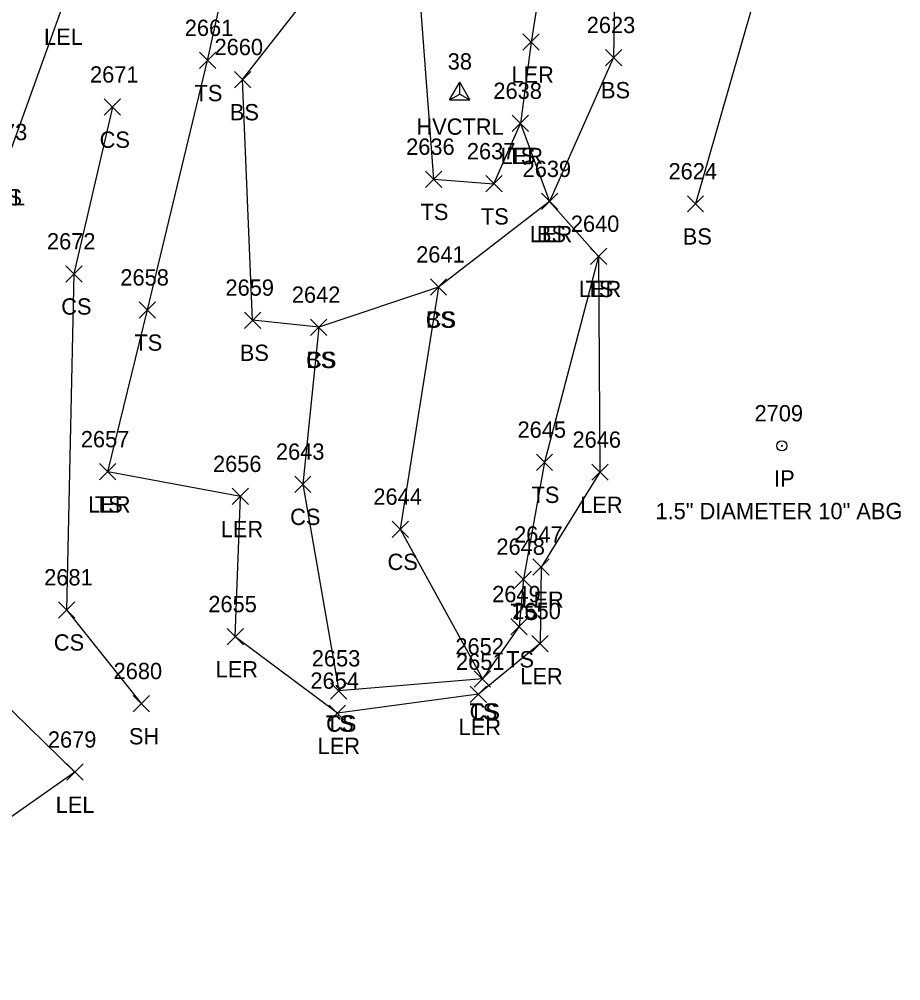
# Model space of a CAD drawing. Extents: x 1483143 to 1488182, y 802902 to 807581.
# Drawn here: x 1487627.8 to 1487735.9, y 805656.4 to 805774.4 of the extents above; entities that cross this region are included whole.
import ezdxf

# ---------------------------------------------------------------- set-up
doc = ezdxf.new("R2010")
doc.units = 0
for name, color, linetype in [('C_A', 7, 'Continuous'), ('C_I', 7, 'Continuous'), ('CPSM', 7, 'Continuous'), ('L_A', 7, 'Continuous'), ('L_I', 7, 'Continuous'), ('L_TIC', 7, 'Continuous'), ('LARO', 7, 'Continuous'), ('LELB', 7, 'Continuous'), ('M_A', 7, 'Continuous'), ('M_C', 7, 'Continuous'), ('M_I', 7, 'Continuous'), ('MPIR', 7, 'Continuous')]:
    doc.layers.add(name, color=color, linetype=linetype)

msp = doc.modelspace()

# ---------------------------------------------------------------- linework, layer by layer
at = {"layer": 'CPSM'}
for p, q in [((1487680.58, 805764.47), (1487681.83, 805766.64)), ((1487683.08, 805764.47), (1487681.83, 805766.64)), ((1487681.83, 805765.19), (1487681.83, 805766.64)), ((1487680.58, 805764.47), (1487681.83, 805765.19)), ((1487680.58, 805764.47), (1487683.08, 805764.47)), ((1487681.83, 805765.19), (1487681.83, 805765.19)), ((1487681.83, 805765.19), (1487683.08, 805764.47))]:
    msp.add_line(p, q, dxfattribs=at)
at = {"layer": 'L_TIC'}
for points in [[(1487689.59, 805770.57), (1487691.59, 805772.57)], [(1487691.59, 805770.57), (1487689.59, 805772.57)], [(1487649.9, 805768.31), (1487651.9, 805770.31)], [(1487651.9, 805768.31), (1487649.9, 805770.31)], [(1487699.71, 805768.66), (1487701.71, 805770.66)], [(1487701.71, 805768.66), (1487699.71, 805770.66)], [(1487654.2, 805765.96), (1487656.2, 805767.96)], [(1487656.2, 805765.96), (1487654.2, 805767.96)], [(1487638.23, 805762.59), (1487640.23, 805764.59)], [(1487640.23, 805762.59), (1487638.23, 805764.59)], [(1487688.27, 805760.59), (1487690.27, 805762.59)], [(1487690.27, 805760.59), (1487688.27, 805762.59)], [(1487688.27, 805760.59), (1487690.27, 805762.59)], [(1487690.27, 805760.59), (1487688.27, 805762.59)], [(1487677.62, 805753.73), (1487679.62, 805755.73)], [(1487679.62, 805753.73), (1487677.62, 805755.73)], [(1487685.02, 805753.18), (1487687.02, 805755.18)], [(1487687.02, 805753.18), (1487685.02, 805755.18)], [(1487691.86, 805751.01), (1487693.86, 805753.01)], [(1487693.86, 805751.01), (1487691.86, 805753.01)], [(1487691.86, 805751.01), (1487693.86, 805753.01)], [(1487693.86, 805751.01), (1487691.86, 805753.01)], [(1487709.75, 805750.72), (1487711.75, 805752.72)], [(1487711.75, 805750.72), (1487709.75, 805752.72)], [(1487697.86, 805744.28), (1487699.86, 805746.28)], [(1487699.86, 805744.28), (1487697.86, 805746.28)], [(1487697.86, 805744.28), (1487699.86, 805746.28)], [(1487699.86, 805744.28), (1487697.86, 805746.28)], [(1487633.52, 805742.13), (1487635.52, 805744.13)], [(1487635.52, 805742.13), (1487633.52, 805744.13)], [(1487678.23, 805740.52), (1487680.23, 805742.52)], [(1487680.23, 805740.52), (1487678.23, 805742.52)], [(1487678.23, 805740.52), (1487680.23, 805742.52)], [(1487680.23, 805740.52), (1487678.23, 805742.52)], [(1487642.52, 805737.7), (1487644.52, 805739.7)], [(1487644.52, 805737.7), (1487642.52, 805739.7)], [(1487655.42, 805736.45), (1487657.42, 805738.45)], [(1487657.42, 805736.45), (1487655.42, 805738.45)], [(1487663.55, 805735.58), (1487665.55, 805737.58)], [(1487665.55, 805735.58), (1487663.55, 805737.58)], [(1487663.55, 805735.58), (1487665.55, 805737.58)], [(1487665.55, 805735.58), (1487663.55, 805737.58)], [(1487691.23, 805719.03), (1487693.23, 805721.03)], [(1487693.23, 805719.03), (1487691.23, 805721.03)], [(1487637.67, 805717.86), (1487639.67, 805719.86)], [(1487639.67, 805717.86), (1487637.67, 805719.86)], [(1487637.67, 805717.86), (1487639.67, 805719.86)], [(1487639.67, 805717.86), (1487637.67, 805719.86)], [(1487698.02, 805717.81), (1487700.02, 805719.81)], [(1487700.02, 805717.81), (1487698.02, 805719.81)], [(1487661.59, 805716.33), (1487663.59, 805718.33)], [(1487663.59, 805716.33), (1487661.59, 805718.33)], [(1487653.93, 805714.83), (1487655.93, 805716.83)], [(1487655.93, 805714.83), (1487653.93, 805716.83)], [(1487673.54, 805710.81), (1487675.54, 805712.81)], [(1487675.54, 805710.81), (1487673.54, 805712.81)], [(1487690.81, 805706.17), (1487692.81, 805708.17)], [(1487692.81, 805706.17), (1487690.81, 805708.17)], [(1487688.64, 805704.67), (1487690.64, 805706.67)], [(1487690.64, 805704.67), (1487688.64, 805706.67)], [(1487632.61, 805700.92), (1487634.61, 805702.92)], [(1487634.61, 805700.92), (1487632.61, 805702.92)], [(1487688.12, 805698.86), (1487690.12, 805700.86)], [(1487690.12, 805698.86), (1487688.12, 805700.86)], [(1487653.3, 805697.63), (1487655.3, 805699.63)], [(1487655.3, 805697.63), (1487653.3, 805699.63)], [(1487690.68, 805696.79), (1487692.68, 805698.79)], [(1487692.68, 805696.79), (1487690.68, 805698.79)], [(1487683.61, 805692.45), (1487685.61, 805694.45)], [(1487685.61, 805692.45), (1487683.61, 805694.45)], [(1487683.61, 805692.45), (1487685.61, 805694.45)], [(1487685.61, 805692.45), (1487683.61, 805694.45)], [(1487666, 805690.98), (1487668, 805692.98)], [(1487668, 805690.98), (1487666, 805692.98)], [(1487666, 805690.98), (1487668, 805692.98)], [(1487668, 805690.98), (1487666, 805692.98)], [(1487683.12, 805690.56), (1487685.12, 805692.56)], [(1487685.12, 805690.56), (1487683.12, 805692.56)], [(1487641.77, 805689.42), (1487643.77, 805691.42)], [(1487643.77, 805689.42), (1487641.77, 805691.42)], [(1487665.83, 805688.24), (1487667.83, 805690.24)], [(1487667.83, 805688.24), (1487665.83, 805690.24)], [(1487633.64, 805681.02), (1487635.64, 805683.02)], [(1487635.64, 805681.02), (1487633.64, 805683.02)]]:
    msp.add_lwpolyline(points, dxfattribs=at)
at = {"layer": 'LARO'}
for points in [[(1487705.29, 805896.34), (1487695.87, 805891.2), (1487689.13, 805878.29), (1487689.57, 805859.67), (1487670.44, 805829.21), (1487659.71, 805823.79), (1487649.08, 805803.93), (1487638.97, 805785.42), (1487633.21, 805776.22), (1487626.14, 805756.53), (1487619.37, 805736.85), (1487617.73, 805704.95), (1487625.22, 805691.16), (1487634.64, 805682.02), (1487622.34, 805673.38), (1487621.2, 805638.86), (1487621.06, 805617.78)], [(1487705.29, 805896.34), (1487704.06, 805875.92), (1487701.89, 805851.18), (1487695.31, 805846.63), (1487693.97, 805826.04), (1487694.06, 805815.15), (1487697.49, 805803.83), (1487704.56, 805795.94), (1487708.81, 805792.59), (1487701.05, 805792.26), (1487694.18, 805794.48), (1487690.59, 805771.57), (1487689.27, 805761.59), (1487692.86, 805752.01), (1487698.86, 805745.28), (1487699.02, 805718.81), (1487691.81, 805707.17), (1487691.68, 805697.79), (1487684.12, 805691.56), (1487666.83, 805689.24), (1487654.3, 805698.63), (1487654.93, 805715.83), (1487638.67, 805718.86)]]:
    msp.add_lwpolyline(points, dxfattribs=at)
at = {"layer": 'LELB'}
for points in [[(1487694.18, 805794.48), (1487693.17, 805806.33), (1487687.93, 805817.69), (1487689.85, 805831.08), (1487691.37, 805841.24), (1487689.57, 805859.67), (1487682.46, 805830.78), (1487680.31, 805810.06), (1487676.2, 805786.76), (1487678.62, 805754.73), (1487686.02, 805754.18), (1487689.27, 805761.59)], [(1487638.67, 805718.86), (1487643.52, 805738.7), (1487650.9, 805769.31), (1487655.79, 805791.53), (1487662.09, 805808.31), (1487670.44, 805829.21)], [(1487701.05, 805792.26), (1487700.71, 805769.66), (1487692.86, 805752.01), (1487679.23, 805741.52), (1487664.55, 805736.58), (1487656.42, 805737.45), (1487655.2, 805766.96), (1487666.09, 805780.93), (1487669.14, 805806.74), (1487670.44, 805829.21)], [(1487719.18, 805781.13), (1487710.75, 805751.72)], [(1487639.23, 805763.59), (1487634.52, 805743.13), (1487633.61, 805701.92)], [(1487698.86, 805745.28), (1487692.23, 805720.03), (1487689.64, 805705.67), (1487689.12, 805699.86), (1487684.61, 805693.45), (1487667, 805691.98)], [(1487679.23, 805741.52), (1487674.54, 805711.81), (1487684.61, 805693.45)], [(1487664.55, 805736.58), (1487662.59, 805717.33), (1487667, 805691.98)], [(1487633.61, 805701.92), (1487642.77, 805690.42)]]:
    msp.add_lwpolyline(points, dxfattribs=at)
at = {"layer": 'MPIR'}
for radius in [0.625, 0.0833]:
    msp.add_circle((1487721.34, 805722.04), radius, dxfattribs=at)

# ---------------------------------------------------------------- texts
at = {"layer": 'C_A'}
msp.add_text('HVCTRL', height=2, dxfattribs=at).set_placement((1487676.52, 805760.19))
at = {"layer": 'C_I'}
msp.add_text('38', height=2, dxfattribs=at).set_placement((1487680.36, 805768.19))
at = {"layer": 'L_A'}
for s, p in [('LEL', (1487630.85, 805771.22)), ('LER', (1487688.17, 805766.57)), ('TS', (1487649.31, 805764.31)), ('BS', (1487699.16, 805764.66)), ('BS', (1487653.64, 805761.96)), ('CS', (1487637.67, 805758.59)), ('LER', (1487686.85, 805756.59)), ('TS', (1487687.68, 805756.59)), ('LEL', (1487623.78, 805751.53)), ('BS', (1487624.58, 805751.53)), ('TS', (1487677.03, 805749.73)), ('TS', (1487684.43, 805749.18)), ('LER', (1487690.44, 805747.01)), ('BS', (1487691.3, 805747.01)), ('BS', (1487709.19, 805746.72)), ('LER', (1487696.44, 805740.28)), ('TS', (1487697.27, 805740.28)), ('CS', (1487632.96, 805738.13)), ('CS', (1487677.67, 805736.52)), ('BS', (1487677.67, 805736.52)), ('TS', (1487641.93, 805733.7)), ('BS', (1487654.86, 805732.45)), ('CS', (1487662.99, 805731.58)), ('BS', (1487662.99, 805731.58)), ('TS', (1487690.64, 805715.03)), ('LER', (1487636.25, 805713.86)), ('TS', (1487637.08, 805713.86)), ('LER', (1487696.6, 805713.81)), ('CS', (1487661.03, 805712.33)), ('LER', (1487652.52, 805710.83)), ('CS', (1487672.98, 805706.81)), ('LER', (1487689.39, 805702.17)), ('TS', (1487688.05, 805700.67)), ('CS', (1487632.05, 805696.92)), ('TS', (1487687.53, 805694.86)), ('LER', (1487651.89, 805693.63)), ('LER', (1487689.26, 805692.79)), ('TS', (1487683.02, 805688.45)), ('CS', (1487683.05, 805688.45)), ('TS', (1487665.41, 805686.98)), ('CS', (1487665.44, 805686.98)), ('LER', (1487681.7, 805686.56)), ('SH', (1487641.26, 805685.42)), ('LER', (1487664.41, 805684.24)), ('LEL', (1487632.28, 805677.02))]:
    msp.add_text(s, height=2, dxfattribs=at).set_placement(p)
at = {"layer": 'L_I'}
for s, p in [('2661', (1487648.11, 805772.31)), ('2623', (1487697.41, 805772.66)), ('2660', (1487651.76, 805769.96)), ('2671', (1487636.49, 805766.59)), ('2638', (1487685.96, 805764.59)), ('2638', (1487685.96, 805764.59)), ('2673', (1487622.84, 805759.53)), ('2673', (1487622.84, 805759.53)), ('2636', (1487675.26, 805757.73)), ('2637', (1487682.71, 805757.18)), ('2639', (1487689.54, 805755.01)), ('2639', (1487689.54, 805755.01)), ('2624', (1487707.44, 805754.72)), ('2640', (1487695.46, 805748.28)), ('2640', (1487695.46, 805748.28)), ('2672', (1487631.21, 805746.13)), ('2641', (1487676.49, 805744.52)), ('2641', (1487676.49, 805744.52)), ('2658', (1487640.21, 805741.7)), ('2659', (1487653.1, 805740.45)), ('2642', (1487661.24, 805739.58)), ('2642', (1487661.24, 805739.58)), ('2645', (1487688.92, 805723.03)), ('2657', (1487635.36, 805721.86)), ('2657', (1487635.36, 805721.86)), ('2646', (1487695.66, 805721.81)), ('2643', (1487659.29, 805720.33)), ('2656', (1487651.57, 805718.83)), ('2644', (1487671.24, 805714.81)), ('2647', (1487688.5, 805710.17)), ('2648', (1487686.33, 805708.67)), ('2681', (1487630.87, 805704.92)), ('2649', (1487685.81, 805702.86)), ('2655', (1487651, 805701.63)), ('2650', (1487688.28, 805700.79)), ('2652', (1487681.3, 805696.45)), ('2652', (1487681.3, 805696.45)), ('2653', (1487663.69, 805694.98)), ('2653', (1487663.69, 805694.98)), ('2651', (1487681.38, 805694.56)), ('2680', (1487639.38, 805693.42)), ('2654', (1487663.52, 805692.24)), ('2679', (1487631.32, 805685.02))]:
    msp.add_text(s, height=2, dxfattribs=at).set_placement(p)
at = {"layer": 'M_A'}
msp.add_text('IP', height=2, dxfattribs=at).set_placement((1487720.39, 805717.04))
at = {"layer": 'M_C'}
msp.add_text('1.5" DIAMETER 10" ABG', height=2, dxfattribs=at).set_placement((1487705.84, 805713.04))
at = {"layer": 'M_I'}
msp.add_text('2709', height=2, dxfattribs=at).set_placement((1487717.99, 805725.04))

doc.saveas('drawing.dxf')
